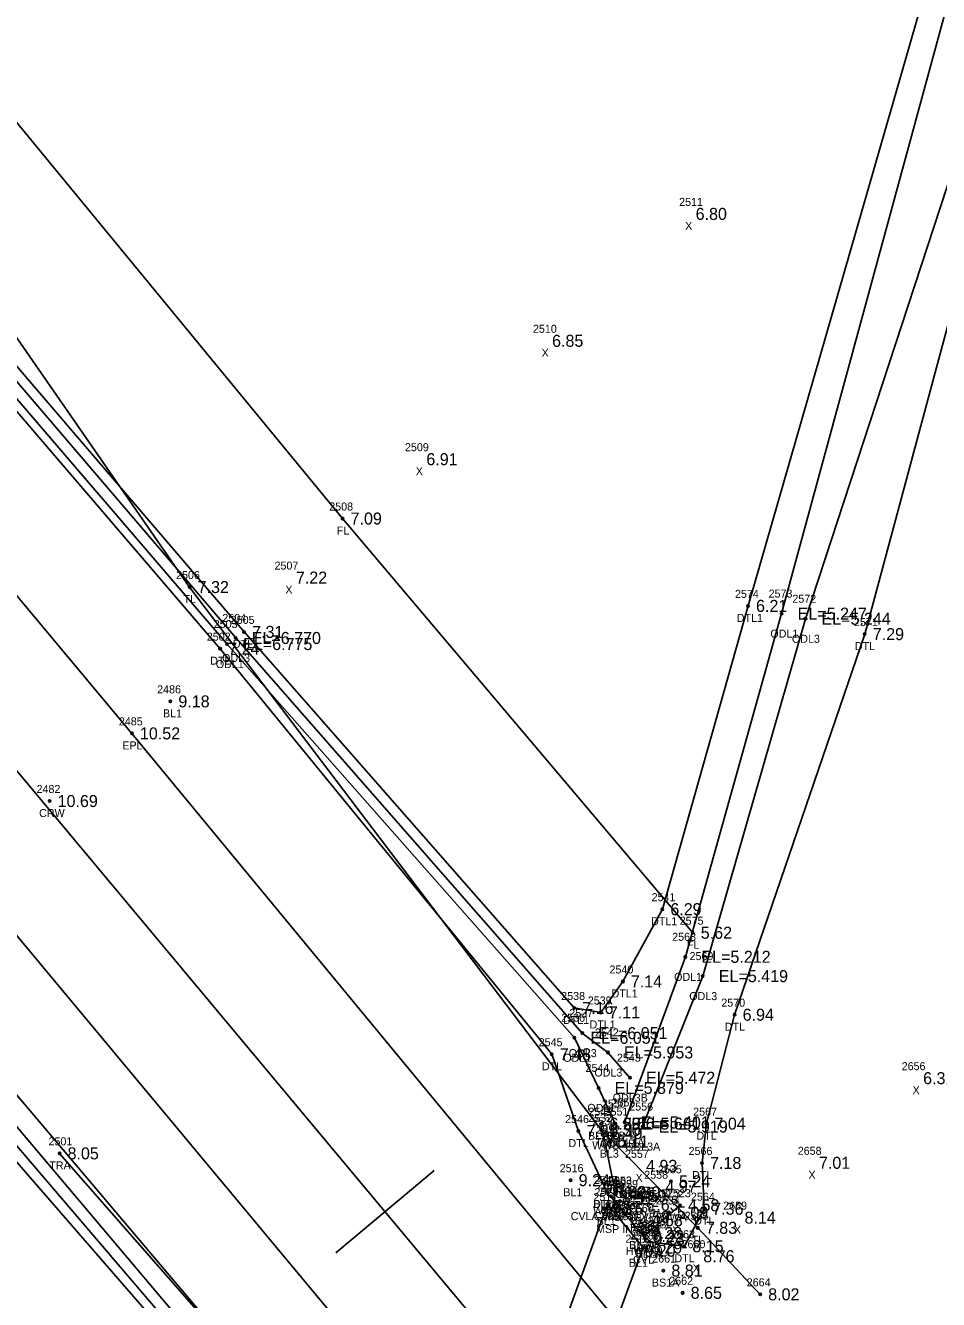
# Model space of a CAD drawing. Extents: x 2042117 to 2045853, y 303080 to 309569.
# Drawn here: x 2044642 to 2044756, y 304432.9 to 304592 of the extents above; entities that cross this region are included whole.
import ezdxf

# ---------------------------------------------------------------- set-up
doc = ezdxf.new("R2010")
doc.units = 0
for name, color, linetype in [('RD_DTM_BkLn_txCode', 7, 'Continuous'), ('RD_EX_Bridge', 7, 'Continuous'), ('RD_EX_Bridge_txCode', 7, 'Continuous'), ('RD_EX_Fence_Other', 7, 'Continuous'), ('RD_EX_Fence_Other_txCode', 7, 'Continuous'), ('RD_EX_H2O', 7, 'Continuous'), ('RD_EX_H2O_txCode', 7, 'Continuous'), ('RD_EX_Misc_txCode', 7, 'Continuous'), ('RD_EX_Road', 7, 'Continuous'), ('RD_EX_Road_txCode', 7, 'Continuous'), ('RD_EX_TX_Bridge_ELEV', 7, 'Continuous'), ('RD_EX_TX_Fence_Other_ELEV', 7, 'Continuous'), ('RD_EX_TX_H2O_ELEV', 7, 'Continuous'), ('RD_EX_TX_Misc_ELEV', 7, 'Continuous'), ('RD_EX_TX_Road_ELEV', 7, 'Continuous'), ('RD_EX_TX_VEG_ELEV', 7, 'Continuous'), ('RD_EX_VEG', 7, 'Continuous'), ('RD_EX_VEG_txCode', 7, 'Continuous'), ('RD_HC_Cl', 7, 'Continuous'), ('RD_HC_Data_Tic', 7, 'Continuous'), ('RD_HC_Survey_ELEV', 7, 'Continuous'), ('RD_HC_Survey_txCode', 7, 'Continuous'), ('RD_SMD_Locator', 7, 'Continuous')]:
    doc.layers.add(name, color=color, linetype=linetype)

msp = doc.modelspace()

# ---------------------------------------------------------------- linework, layer by layer
at = {"layer": 'RD_EX_Bridge'}
for p, q in [((2044719.44, 304440.47), (2044715.11, 304445.78)), ((2044723.74, 304444.68), (2044719.31, 304440.84))]:
    msp.add_line(p, q, dxfattribs=at)
for points in [[(2044715.47, 304445.55), (2044715.7, 304446.16), (2044714.15, 304453.67)], [(2044714.68, 304444.82), (2044719.12, 304439.4), (2044701.71, 304391.61), (2044697.34, 304396.91), (2044714.68, 304444.82)]]:
    msp.add_lwpolyline(points, dxfattribs=at)
at = {"layer": 'RD_EX_Fence_Other'}
msp.add_lwpolyline([(2044487.63, 304762.15), (2044554.33, 304682.4), (2044620.57, 304604.64), (2044681.6, 304530.46), (2044725.33, 304478.72)], dxfattribs=at)
at = {"layer": 'RD_EX_H2O'}
for points in [[(2044415.25, 304826.5), (2044425.66, 304808.25), (2044476.98, 304747.65), (2044539.62, 304670.39), (2044605.13, 304591.24), (2044669.3, 304516.3), (2044710.53, 304469.32), (2044713.85, 304468.76), (2044716.6, 304472.63), (2044721.53, 304481.66), (2044732.23, 304519.55), (2044759.21, 304613.29), (2044789.62, 304712.59), (2044819.6, 304810.16), (2044847.46, 304908.11)], [(2044716.81, 304455.02), (2044724.41, 304475.71), (2044736.43, 304518.58), (2044762.06, 304612.81), (2044791.72, 304711.72), (2044823.39, 304808.82), (2044851.52, 304906.14)], [(2044719.06, 304454.51), (2044726.58, 304473.3), (2044739.4, 304517.94), (2044769.91, 304611.11), (2044797.28, 304709.9), (2044827.72, 304807.52), (2044855.71, 304905.79)], [(2044719.89, 304440.12), (2044724.28, 304439.56), (2044726.76, 304444.25), (2044726.49, 304449.96), (2044727.04, 304454.87), (2044730.56, 304468.48), (2044746.81, 304516.02), (2044772.02, 304609.79), (2044801.76, 304708.94), (2044831.05, 304807.04), (2044857.93, 304905.05)], [(2044411.61, 304823.92), (2044423.39, 304807.22), (2044471.39, 304742.74), (2044536.14, 304667.19), (2044602.88, 304589.74), (2044667.18, 304514.78), (2044710.55, 304465.6), (2044713.57, 304459.34), (2044715.66, 304454.88)], [(2044412.68, 304824.61), (2044424.35, 304807.8), (2044474.04, 304744.84), (2044537.22, 304668.23), (2044604.12, 304590.58), (2044668.25, 304515.54), (2044711.53, 304466.18), (2044714.74, 304463.76), (2044717.49, 304460.61)], [(2044410.56, 304822.99), (2044421.91, 304806.08), (2044470.67, 304741.87), (2044535.46, 304666.28), (2044602.12, 304589.07), (2044666.31, 304514.2), (2044707.72, 304463.54), (2044711.05, 304453.94), (2044714.6, 304446.34)], [(2044526.69, 304588.12), (2044529.75, 304589.5), (2044560.23, 304553.15), (2044624.26, 304478.07), (2044679.39, 304412.98), (2044689.21, 304400.4), (2044696.61, 304396.14)], [(2044526.69, 304588.12), (2044524.46, 304585.8), (2044557.52, 304549.44), (2044620.27, 304473.78), (2044676.08, 304409.54), (2044675.89, 304404.78), (2044683.56, 304394.92), (2044688.93, 304389.15), (2044690.58, 304383.03), (2044681.72, 304360.31), (2044669.72, 304323.23)], [(2044526.69, 304586.11), (2044558.35, 304550.68), (2044621.04, 304475.29), (2044676.74, 304410.12), (2044678.19, 304404.53), (2044685.26, 304396.55), (2044691.41, 304390.93)], [(2044528.02, 304587.51), (2044559.1, 304551.6), (2044622.39, 304476.37), (2044677.57, 304411.07), (2044687.25, 304399.14), (2044692.5, 304393.31)]]:
    msp.add_lwpolyline(points, dxfattribs=at)
at = {"layer": 'RD_EX_Road'}
for points in [[(2043522.11, 305820), (2043547.67, 305789.85), (2043610.72, 305713.32), (2043674.95, 305636.32), (2043738.18, 305559.62), (2043802.42, 305482.71), (2043865.72, 305405.84), (2043929.53, 305328.85), (2043994.13, 305253.28), (2044057.4, 305176.5), (2044121.27, 305100.2), (2044185.29, 305023.54), (2044249.56, 304947.28), (2044313.31, 304870.31), (2044377.09, 304793.29), (2044442, 304716.26), (2044505.92, 304639.55), (2044570.44, 304562.35), (2044634.61, 304485.93), (2044698.46, 304409.27), (2044762.46, 304332.37)], [(2044395.5, 304814.18), (2044398.16, 304811.09), (2044461.8, 304734.03), (2044526.04, 304657.6), (2044591.28, 304580.23), (2044655.29, 304503.62), (2044718.26, 304427.32), (2044783.13, 304349.86)]]:
    msp.add_lwpolyline(points, dxfattribs=at)
at = {"layer": 'RD_EX_VEG'}
for points in [[(2044387.58, 304996.88), (2044390.53, 304961.86), (2044388.93, 304944.71), (2044397.82, 304931.38), (2044395.87, 304907.56), (2044407.42, 304883.17), (2044412.64, 304877.39), (2044413.34, 304846.91), (2044417.62, 304826.21), (2044417.53, 304827.99), (2044425.41, 304820.87), (2044430.68, 304811.06), (2044486.4, 304757.95), (2044546.53, 304677.07), (2044611.02, 304596.16), (2044662.5, 304521.9), (2044713.91, 304454.08), (2044725.96, 304441.86), (2044733.75, 304433.55)], [(2044646.25, 304451.16), (2044692.59, 304398.27), (2044689.62, 304390.75), (2044702.2, 304378.53)]]:
    msp.add_lwpolyline(points, dxfattribs=at)
at = {"layer": 'RD_HC_Cl'}
msp.add_line((2043284.3, 306123.24), (2045221.31, 303804), dxfattribs=at)
at = {"layer": 'RD_HC_Data_Tic'}
for q in [(2044693.03, 304449), (2044680.75, 304438.74)]:
    msp.add_line((2044686.89, 304443.87), q, dxfattribs=at)
at = {"layer": 'RD_SMD_Locator'}
for centre in [(2044681.6, 304530.46), (2044662.5, 304521.9), (2044732.23, 304519.55), (2044736.43, 304518.58), (2044739.4, 304517.94), (2044669.3, 304516.3), (2044746.81, 304516.02), (2044667.18, 304514.78), (2044668.25, 304515.54), (2044666.31, 304514.2), (2044660.09, 304507.62), (2044655.29, 304503.62), (2044645.01, 304495.17), (2044721.53, 304481.66), (2044725.33, 304478.72), (2044724.41, 304475.71), (2044726.58, 304473.3), (2044716.6, 304472.63), (2044710.53, 304469.32), (2044713.85, 304468.76), (2044730.56, 304468.48), (2044710.55, 304465.6), (2044711.53, 304466.18), (2044707.72, 304463.54), (2044714.74, 304463.76), (2044717.49, 304460.61), (2044713.57, 304459.34), (2044711.05, 304453.94), (2044713.91, 304454.08), (2044713.92, 304454.86), (2044715.66, 304454.88), (2044715.66, 304454.88), (2044716.81, 304455.02), (2044719.06, 304454.51), (2044727.04, 304454.87), (2044714.15, 304453.67), (2044714.92, 304452.64), (2044646.25, 304451.16), (2044726.49, 304449.96), (2044710.08, 304447.81), (2044722.61, 304447.67), (2044714.6, 304446.34), (2044714.6, 304446.34), (2044715.7, 304446.16), (2044716.38, 304446.27), (2044714.68, 304444.82), (2044714.68, 304444.82), (2044715.11, 304445.78), (2044715.47, 304445.55), (2044716.23, 304445.21), (2044723.74, 304444.68), (2044714.26, 304444.21), (2044722.36, 304443.78), (2044726.76, 304444.25), (2044719.09, 304441.21), (2044725.96, 304441.86), (2044719.31, 304440.84), (2044719.44, 304440.47), (2044719.89, 304440.12), (2044719.89, 304440.12), (2044724.28, 304439.56), (2044718.28, 304439), (2044719.12, 304439.4), (2044721.66, 304436.52), (2044724.07, 304433.74), (2044733.75, 304433.55)]:
    msp.add_circle(centre, 0.15, dxfattribs=at)

# ---------------------------------------------------------------- texts
at = {"layer": 'RD_DTM_BkLn_txCode'}
for s, p in [('2486', (2044658.44, 304508.62)), ('BL1', (2044659.17, 304505.62)), ('2549', (2044712.29, 304455.86)), ('2551', (2044714.32, 304455.88)), ('2552', (2044713.29, 304453.64)), ('BL2B', (2044712.25, 304452.86)), ('BL3', (2044714.46, 304452.88)), ('BL3', (2044713.72, 304450.64)), ('2516', (2044708.71, 304448.81)), ('2535', (2044720.98, 304448.67)), ('2548', (2044712.97, 304447.34)), ('2553', (2044714.75, 304447.27)), ('BL1', (2044709.16, 304445.81)), ('2517', (2044712.92, 304445.21)), ('2554', (2044714.6, 304446.21)), ('BL3', (2044721.4, 304445.67)), ('BL2A', (2044712.91, 304444.34)), ('BL3', (2044715.17, 304444.27)), ('2534', (2044720.73, 304444.78)), ('BL1', (2044713.34, 304442.21)), ('BL3B', (2044714.55, 304443.21)), ('2533', (2044717.46, 304442.21)), ('2561', (2044718.52, 304441.12)), ('BL3', (2044721.16, 304441.78)), ('2518', (2044716.93, 304440)), ('BL3A', (2044717.4, 304439.21)), ('BL2A', (2044718.2, 304438.12)), ('2661', (2044720.27, 304437.52)), ('BL1', (2044717.36, 304437)), ('BS1A', (2044720.23, 304434.52)), ('2662', (2044722.39, 304434.74))]:
    msp.add_text(s, height=1, dxfattribs=at).set_placement(p)
at = {"layer": 'RD_EX_Bridge_txCode'}
for s, p in [('2531', (2044712.8, 304454.67)), ('WWB', (2044712.77, 304451.67)), ('2526', (2044713.45, 304446.78)), ('2530', (2044714.03, 304447.16)), ('2527', (2044713.05, 304445.82)), ('2578', (2044713.05, 304445.82)), ('2529', (2044713.84, 304446.55)), ('2523', (2044722.11, 304445.68)), ('WWA .6', (2044712.87, 304443.55)), ('HWB', (2044713.82, 304443.78)), ('WW', (2044714.79, 304444.16)), ('CVLA 5HX5W', (2044710.09, 304442.82)), ('CVLB', (2044712.96, 304442.82)), ('2524', (2044717.68, 304441.84)), ('WWA .6', (2044721.15, 304442.68)), ('2528', (2044717.49, 304440.4)), ('2525', (2044717.81, 304441.47)), ('WWB', (2044717.93, 304438.84)), ('HWA .9', (2044716.95, 304438.47)), ('CVL', (2044717.88, 304437.4))]:
    msp.add_text(s, height=1, dxfattribs=at).set_placement(p)
at = {"layer": 'RD_EX_Fence_Other_txCode'}
for s, p in [('2508', (2044679.93, 304531.46)), ('FL', (2044680.87, 304528.46)), ('2575', (2044723.7, 304479.72)), ('FL', (2044724.6, 304476.72))]:
    msp.add_text(s, height=1, dxfattribs=at).set_placement(p)
at = {"layer": 'RD_EX_H2O_txCode'}
for s, p in [('2574', (2044730.6, 304520.55)), ('2573', (2044734.8, 304520.58)), ('2572', (2044737.77, 304519.94)), ('2503', (2044665.51, 304516.78)), ('2504', (2044666.58, 304517.54)), ('2505', (2044667.63, 304517.3)), ('DTL1', (2044730.82, 304517.55)), ('2571', (2044745.46, 304517.02)), ('2502', (2044664.64, 304515.2)), ('ODL1', (2044735.02, 304515.58)), ('DTL1', (2044667.89, 304514.3)), ('ODL3', (2044737.71, 304514.94)), ('DTL', (2044745.57, 304514.02)), ('DTL', (2044665.07, 304512.2)), ('ODL3', (2044666.55, 304512.54)), ('ODL1', (2044665.77, 304511.78)), ('2541', (2044720.19, 304482.66)), ('DTL1', (2044720.12, 304479.66)), ('2568', (2044722.76, 304477.71)), ('2569', (2044724.93, 304475.3)), ('2540', (2044714.93, 304473.63)), ('ODL1', (2044723, 304472.71)), ('DTL1', (2044715.19, 304470.63)), ('2538', (2044708.9, 304470.32)), ('2539', (2044712.22, 304469.76)), ('ODL3', (2044724.89, 304470.3)), ('2570', (2044728.9, 304469.48)), ('2536', (2044708.9, 304467.6)), ('DTL1', (2044709.12, 304467.32)), ('2537', (2044709.9, 304468.18)), ('DTL1', (2044712.44, 304466.76)), ('2542', (2044713.11, 304465.76)), ('DTL', (2044729.32, 304466.48)), ('2545', (2044706.09, 304464.54)), ('ODL1', (2044709.15, 304462.6)), ('ODL3', (2044709.84, 304463.18)), ('2543', (2044715.86, 304462.61)), ('DTL', (2044706.48, 304461.54)), ('2544', (2044711.94, 304461.34)), ('ODL3', (2044713.04, 304460.76)), ('ODL1', (2044712.16, 304456.34)), ('2550', (2044713.99, 304456.88)), ('2555', (2044715.18, 304457.02)), ('ODL3B', (2044715.33, 304457.61)), ('2556', (2044717.4, 304456.51)), ('2546', (2044709.39, 304454.94)), ('2567', (2044725.38, 304455.87)), ('DTL', (2044709.8, 304451.94)), ('ODL1B', (2044713.78, 304451.88)), ('ODL1A', (2044714.91, 304452.02)), ('ODL3A', (2044716.88, 304451.51)), ('DTL', (2044725.79, 304452.87)), ('2566', (2044724.81, 304450.96)), ('2547', (2044712.97, 304447.34)), ('DTL', (2044725.24, 304447.96)), ('2564', (2044725.1, 304445.25)), ('DTLB', (2044712.88, 304444.34)), ('DTL', (2044725.51, 304442.25)), ('2562', (2044718.24, 304441.12)), ('2563', (2044722.63, 304440.56)), ('DTLA', (2044718.16, 304438.12)), ('DTL', (2044723.04, 304437.56))]:
    msp.add_text(s, height=1, dxfattribs=at).set_placement(p)
at = {"layer": 'RD_EX_Misc_txCode'}
for s, p in [('2511', (2044723.63, 304569.51)), ('X', (2044724.38, 304566.51)), ('2510', (2044705.37, 304553.66)), ('X', (2044706.45, 304550.66)), ('2509', (2044689.39, 304538.87)), ('X', (2044690.74, 304535.87)), ('2507', (2044673.1, 304524.08)), ('X', (2044674.45, 304521.08)), ('2656', (2044751.42, 304461.55)), ('X', (2044752.78, 304458.55)), ('2557', (2044716.87, 304450.6)), ('2658', (2044738.44, 304450.98)), ('2559', (2044715.52, 304446.84)), ('X', (2044718.18, 304447.6)), ('2558', (2044719.27, 304447.99)), ('X', (2044739.78, 304447.98)), ('2521', (2044717.32, 304445.74)), ('2522', (2044715.94, 304444.21)), ('X', (2044716.84, 304443.84)), ('2560', (2044717.48, 304443.81)), ('X', (2044720.58, 304444.99)), ('2659', (2044729.13, 304444.13)), ('MSP INVERT', (2044714.34, 304442.74)), ('MSP INVERT', (2044713.25, 304441.21)), ('X', (2044718.86, 304440.81)), ('X', (2044730.47, 304441.13)), ('2660', (2044723.93, 304439.31)), ('X', (2044725.33, 304436.31))]:
    msp.add_text(s, height=1, dxfattribs=at).set_placement(p)
at = {"layer": 'RD_EX_Road_txCode'}
for s, p in [('2485', (2044653.66, 304504.62)), ('EPL', (2044654.09, 304501.62))]:
    msp.add_text(s, height=1, dxfattribs=at).set_placement(p)
at = {"layer": 'RD_EX_TX_Bridge_ELEV'}
for s, p in [('5.49', (2044715.15, 304452.92)), ('9.24', (2044716.11, 304445.03)), ('8.31', (2044716.47, 304444.8)), ('8.25', (2044716.7, 304445.41)), ('8.20', (2044715.68, 304444.07)), ('8.20', (2044715.68, 304444.07)), ('4.58', (2044724.74, 304443.93)), ('8.22', (2044720.31, 304440.09)), ('9.23', (2044720.44, 304439.72)), ('8.29', (2044720.12, 304438.65))]:
    msp.add_text(s, height=1.5, dxfattribs=at).set_placement(p)
at = {"layer": 'RD_EX_TX_Fence_Other_ELEV'}
for s, p in [('7.09', (2044682.6, 304529.71)), ('5.62', (2044726.33, 304477.97))]:
    msp.add_text(s, height=1.5, dxfattribs=at).set_placement(p)
at = {"layer": 'RD_EX_TX_H2O_ELEV'}
for s, p in [('6.21', (2044733.23, 304518.8)), ('EL=5.247', (2044738.43, 304517.83)), ('EL=5.244', (2044741.4, 304517.19)), ('7.31', (2044670.3, 304515.55)), ('EL=6.770', (2044670.25, 304514.79)), ('7.29', (2044747.81, 304515.27)), ('7.24', (2044667.31, 304513.45)), ('EL=6.775', (2044669.18, 304514.03)), ('6.29', (2044722.53, 304480.91)), ('EL=5.212', (2044726.41, 304474.96)), ('7.14', (2044717.6, 304471.88)), ('EL=5.419', (2044728.58, 304472.55)), ('7.16', (2044711.53, 304468.57)), ('7.11', (2044714.85, 304468.01)), ('6.94', (2044731.56, 304467.73)), ('EL=6.051', (2044713.53, 304465.43)), ('EL=6.051', (2044712.55, 304464.85)), ('7.48', (2044708.72, 304462.79)), ('EL=5.953', (2044716.74, 304463.01)), ('EL=5.472', (2044719.49, 304459.86)), ('EL=5.879', (2044715.57, 304458.59)), ('EL=5.661', (2044717.66, 304454.13)), ('EL=5.401', (2044718.81, 304454.27)), ('7.04', (2044728.04, 304454.12)), ('7.81', (2044712.05, 304453.19)), ('EL=5.919', (2044721.06, 304453.76)), ('7.18', (2044727.49, 304449.21)), ('8.32', (2044715.6, 304445.59)), ('7.36', (2044727.76, 304443.5)), ('8.69', (2044720.89, 304439.37)), ('8.15', (2044725.28, 304438.81))]:
    msp.add_text(s, height=1.5, dxfattribs=at).set_placement(p)
at = {"layer": 'RD_EX_TX_Misc_ELEV'}
for s, p in [('6.80', (2044725.69, 304567.76)), ('6.85', (2044707.76, 304551.91)), ('6.91', (2044692.06, 304537.12)), ('7.22', (2044675.77, 304522.33)), ('9.18', (2044661.09, 304506.87)), ('6.31', (2044754.1, 304459.8)), ('6.20', (2044714.92, 304454.11)), ('5.66', (2044716.66, 304454.13)), ('5.11', (2044715.92, 304451.89)), ('4.93', (2044719.5, 304448.85)), ('7.01', (2044741.09, 304449.23)), ('9.24', (2044711.08, 304447.06)), ('4.97', (2044721.9, 304446.24)), ('5.24', (2044723.61, 304446.92)), ('8.32', (2044715.6, 304445.59)), ('4.59', (2044717.38, 304445.52)), ('4.59', (2044718.15, 304445.09)), ('9.16', (2044715.26, 304443.46)), ('4.42', (2044717.23, 304444.46)), ('2.63', (2044719.66, 304443.99)), ('5.09', (2044723.36, 304443.03)), ('2.59', (2044718.57, 304442.46)), ('4.58', (2044720.18, 304442.06)), ('8.14', (2044731.79, 304442.38)), ('4.28', (2044720.09, 304440.46)), ('9.20', (2044719.28, 304438.25)), ('8.69', (2044720.89, 304439.37)), ('8.76', (2044726.64, 304437.56)), ('8.81', (2044722.66, 304435.77)), ('8.65', (2044725.07, 304432.99))]:
    msp.add_text(s, height=1.5, dxfattribs=at).set_placement(p)
at = {"layer": 'RD_EX_TX_Road_ELEV'}
msp.add_text('10.52', height=1.5, dxfattribs=at).set_placement((2044656.29, 304502.87))
at = {"layer": 'RD_EX_TX_VEG_ELEV'}
for s, p in [('7.32', (2044663.5, 304521.15)), ('6.30', (2044714.91, 304453.33)), ('8.05', (2044647.25, 304450.41)), ('7.83', (2044726.96, 304441.11)), ('8.02', (2044734.75, 304432.8))]:
    msp.add_text(s, height=1.5, dxfattribs=at).set_placement(p)
at = {"layer": 'RD_EX_VEG_txCode'}
for s, p in [('2506', (2044660.8, 304522.9)), ('TL', (2044661.73, 304519.9)), ('2532', (2044712.28, 304455.08)), ('2501', (2044644.87, 304452.16)), ('TL', (2044713.14, 304452.08)), ('TRA', (2044644.97, 304449.16)), ('2565', (2044724.31, 304442.86)), ('TL', (2044725.19, 304439.86)), ('2664', (2044732.07, 304434.55))]:
    msp.add_text(s, height=1, dxfattribs=at).set_placement(p)
at = {"layer": 'RD_HC_Survey_ELEV'}
msp.add_text('10.69', height=1.5, dxfattribs=at).set_placement((2044646.01, 304494.42))
at = {"layer": 'RD_HC_Survey_txCode'}
for s, p in [('2482', (2044643.38, 304496.17)), ('CRW', (2044643.7, 304493.17))]:
    msp.add_text(s, height=1, dxfattribs=at).set_placement(p)

doc.saveas('drawing.dxf')
